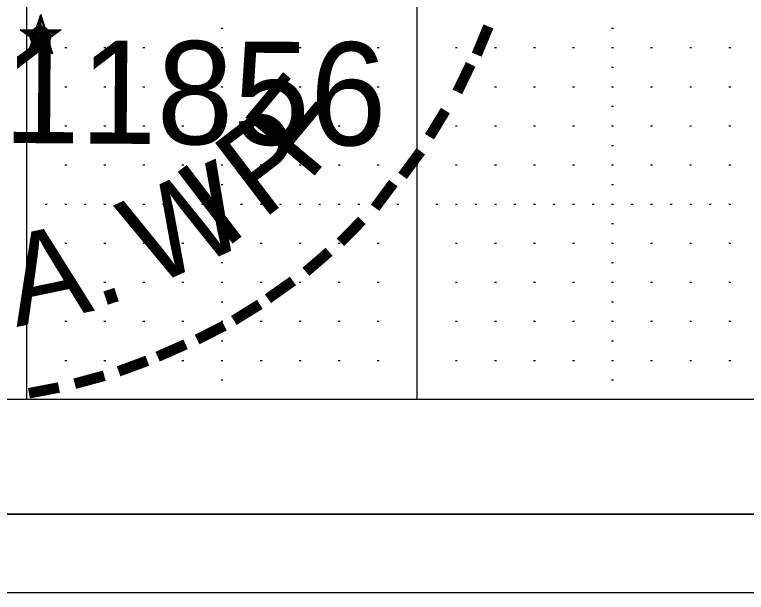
# Model space of a CAD drawing. Extents: x -1.3 to 32.1, y -0.2 to 20.7.
# Drawn here: x 23.714 to 25.588, y -0.2 to 1.277 of the extents above; entities that cross this region are included whole.
import ezdxf

# ---------------------------------------------------------------- set-up
doc = ezdxf.new("R2010")
doc.units = 0
for name, color, linetype in [('Level 1', 7, 'Continuous'), ('Level 37', 7, 'Continuous'), ('Level 49', 7, 'Continuous'), ('Level 5', 7, 'Continuous'), ('Level 50', 7, 'Continuous'), ('Level 6', 7, 'Continuous'), ('Level 62', 7, 'Continuous'), ('Level 63', 7, 'Continuous')]:
    doc.layers.add(name, color=color, linetype=linetype)

msp = doc.modelspace()

# ---------------------------------------------------------------- linework, layer by layer
at = {"layer": 'Level 1'}
msp.add_line((31.617, -0.001), (-0.001, -0.001), dxfattribs=at)
at = {"layer": 'Level 37'}
msp.add_line((31.618, -0.001), (-0.001, -0.001), dxfattribs=at)
at = {"layer": 'Level 49'}
for p, q in [((23.7815, 1.2774), (23.7722, 1.2386)), ((23.7815, 1.2774), (23.7741, 1.2386)), ((23.7815, 1.2774), (23.7778, 1.2386)), ((23.7815, 1.2201), (23.7815, 1.2774)), ((23.7815, 1.2774), (23.7889, 1.2386)), ((23.7815, 1.2774), (23.7889, 1.2386)), ((23.7815, 1.2774), (23.7815, 1.2386)), ((23.7278, 1.2386), (23.7815, 1.2201)), ((23.7278, 1.2386), (23.7667, 1.2349)), ((23.7278, 1.2386), (23.7667, 1.2312)), ((23.7278, 1.2386), (23.7648, 1.2275)), ((23.7278, 1.2386), (23.7648, 1.2238)), ((23.7278, 1.2386), (23.763, 1.2201)), ((23.7278, 1.2386), (23.763, 1.2164)), ((23.8333, 1.2386), (23.7815, 1.2201)), ((23.8333, 1.2386), (23.787, 1.2349)), ((23.8333, 1.2386), (23.7889, 1.2312)), ((23.8333, 1.2386), (23.7889, 1.2275)), ((23.8333, 1.2386), (23.8, 1.2256)), ((23.8333, 1.2386), (23.8018, 1.2201)), ((23.8333, 1.2386), (23.8037, 1.2201)), ((23.7482, 1.1775), (23.7815, 1.2201)), ((23.7482, 1.1775), (23.7648, 1.2201)), ((23.8111, 1.1775), (23.7815, 1.2201)), ((23.8111, 1.1775), (23.7926, 1.2201)), ((23.8111, 1.1775), (23.7944, 1.2201)), ((23.7482, 1.1775), (23.7667, 1.2127)), ((23.7482, 1.1775), (23.7704, 1.2127)), ((23.7482, 1.1775), (23.7741, 1.209)), ((23.7482, 1.1775), (23.7796, 1.209)), ((23.7482, 1.1775), (23.7815, 1.2053)), ((23.8111, 1.1775), (23.7796, 1.209)), ((23.8111, 1.1775), (23.7796, 1.2053)), ((23.8111, 1.1775), (23.7852, 1.209)), ((23.8111, 1.1775), (23.7889, 1.2127))]:
    msp.add_line(p, q, dxfattribs=at)
msp.add_lwpolyline([(23.7815, 1.2774), (23.8111, 1.1775), (23.7278, 1.2386), (23.8333, 1.2386), (23.7482, 1.1775), (23.7815, 1.2774)], dxfattribs=at)
for radius in [0.0258, 0.0234, 0.0217, 0.0199, 0.0173, 0.0161, 0.0149, 0.0128, 0.0112, 0.00931, 0.00743, 0.00554, 0.00444, 0.00216]:
    msp.add_circle((23.7802, 1.2214), radius, dxfattribs=at)
at = {"layer": 'Level 5'}
for p, q in [((24.2425, 1.243), (24.2475, 1.243)), ((25.2425, 1.243), (25.2475, 1.243)), ((23.8425, 1.193), (23.8475, 1.193)), ((23.9425, 1.193), (23.9475, 1.193)), ((24.0425, 1.193), (24.0475, 1.193)), ((24.1425, 1.193), (24.1475, 1.193)), ((24.2425, 1.193), (24.2475, 1.193)), ((24.3425, 1.193), (24.3475, 1.193)), ((24.4425, 1.193), (24.4475, 1.193)), ((24.5425, 1.193), (24.5475, 1.193)), ((24.6425, 1.193), (24.6475, 1.193)), ((24.8425, 1.193), (24.8475, 1.193)), ((24.9425, 1.193), (24.9475, 1.193)), ((25.0425, 1.193), (25.0475, 1.193)), ((25.1425, 1.193), (25.1475, 1.193)), ((25.2425, 1.193), (25.2475, 1.193)), ((25.3425, 1.193), (25.3475, 1.193)), ((25.4425, 1.193), (25.4475, 1.193)), ((25.5425, 1.193), (25.5475, 1.193)), ((24.2425, 1.143), (24.2475, 1.143)), ((25.2425, 1.143), (25.2475, 1.143)), ((23.8425, 1.093), (23.8475, 1.093)), ((23.9425, 1.093), (23.9475, 1.093)), ((24.0425, 1.093), (24.0475, 1.093)), ((24.1425, 1.093), (24.1475, 1.093)), ((24.2425, 1.093), (24.2475, 1.093)), ((24.3425, 1.093), (24.3475, 1.093)), ((24.4425, 1.093), (24.4475, 1.093)), ((24.5425, 1.093), (24.5475, 1.093)), ((24.6425, 1.093), (24.6475, 1.093)), ((24.8425, 1.093), (24.8475, 1.093)), ((24.9425, 1.093), (24.9475, 1.093)), ((25.0425, 1.093), (25.0475, 1.093)), ((25.1425, 1.093), (25.1475, 1.093)), ((25.2425, 1.093), (25.2475, 1.093)), ((25.3425, 1.093), (25.3475, 1.093)), ((25.4425, 1.093), (25.4475, 1.093)), ((25.5425, 1.093), (25.5475, 1.093)), ((24.2425, 1.043), (24.2475, 1.043)), ((25.2425, 1.043), (25.2475, 1.043)), ((23.8425, 0.993), (23.8475, 0.993)), ((23.9425, 0.993), (23.9475, 0.993)), ((24.0425, 0.993), (24.0475, 0.993)), ((24.1425, 0.993), (24.1475, 0.993)), ((24.2425, 0.993), (24.2475, 0.993)), ((24.3425, 0.993), (24.3475, 0.993)), ((24.4425, 0.993), (24.4475, 0.993)), ((24.5425, 0.993), (24.5475, 0.993)), ((24.6425, 0.993), (24.6475, 0.993)), ((24.8425, 0.993), (24.8475, 0.993)), ((24.9425, 0.993), (24.9475, 0.993)), ((25.0425, 0.993), (25.0475, 0.993)), ((25.1425, 0.993), (25.1475, 0.993)), ((25.2425, 0.993), (25.2475, 0.993)), ((25.3425, 0.993), (25.3475, 0.993)), ((25.4425, 0.993), (25.4475, 0.993)), ((25.5425, 0.993), (25.5475, 0.993)), ((24.2425, 0.943), (24.2475, 0.943)), ((25.2425, 0.943), (25.2475, 0.943)), ((23.8425, 0.893), (23.8475, 0.893)), ((23.9425, 0.893), (23.9475, 0.893)), ((24.0425, 0.893), (24.0475, 0.893)), ((24.1425, 0.893), (24.1475, 0.893)), ((24.2425, 0.893), (24.2475, 0.893)), ((24.3425, 0.893), (24.3475, 0.893)), ((24.4425, 0.893), (24.4475, 0.893)), ((24.5425, 0.893), (24.5475, 0.893)), ((24.6425, 0.893), (24.6475, 0.893)), ((24.8425, 0.893), (24.8475, 0.893)), ((24.9425, 0.893), (24.9475, 0.893)), ((25.0425, 0.893), (25.0475, 0.893)), ((25.1425, 0.893), (25.1475, 0.893)), ((25.2425, 0.893), (25.2475, 0.893)), ((25.3425, 0.893), (25.3475, 0.893)), ((25.4425, 0.893), (25.4475, 0.893)), ((25.5425, 0.893), (25.5475, 0.893)), ((24.2425, 0.843), (24.2475, 0.843)), ((25.2425, 0.843), (25.2475, 0.843)), ((23.7925, 0.793), (23.7975, 0.793)), ((23.8425, 0.793), (23.8475, 0.793)), ((23.8925, 0.793), (23.8975, 0.793)), ((23.9425, 0.793), (23.9475, 0.793)), ((23.9925, 0.793), (23.9975, 0.793)), ((24.0425, 0.793), (24.0475, 0.793)), ((24.0925, 0.793), (24.0975, 0.793)), ((24.1425, 0.793), (24.1475, 0.793)), ((24.1925, 0.793), (24.1975, 0.793)), ((24.2425, 0.793), (24.2475, 0.793)), ((24.2925, 0.793), (24.2975, 0.793)), ((24.3425, 0.793), (24.3475, 0.793)), ((24.3925, 0.793), (24.3975, 0.793)), ((24.4425, 0.793), (24.4475, 0.793)), ((24.4925, 0.793), (24.4975, 0.793)), ((24.5425, 0.793), (24.5475, 0.793)), ((24.5925, 0.793), (24.5975, 0.793)), ((24.6425, 0.793), (24.6475, 0.793)), ((24.6925, 0.793), (24.6975, 0.793)), ((24.7925, 0.793), (24.7975, 0.793)), ((24.8425, 0.793), (24.8475, 0.793)), ((24.8925, 0.793), (24.8975, 0.793)), ((24.9425, 0.793), (24.9475, 0.793)), ((24.9925, 0.793), (24.9975, 0.793)), ((25.0425, 0.793), (25.0475, 0.793)), ((25.0925, 0.793), (25.0975, 0.793)), ((25.1425, 0.793), (25.1475, 0.793)), ((25.1925, 0.793), (25.1975, 0.793)), ((25.2425, 0.793), (25.2475, 0.793)), ((25.2925, 0.793), (25.2975, 0.793)), ((25.3425, 0.793), (25.3475, 0.793)), ((25.3925, 0.793), (25.3975, 0.793)), ((25.4425, 0.793), (25.4475, 0.793)), ((25.4925, 0.793), (25.4975, 0.793)), ((25.5425, 0.793), (25.5475, 0.793)), ((24.2425, 0.743), (24.2475, 0.743)), ((25.2425, 0.743), (25.2475, 0.743)), ((23.8425, 0.693), (23.8475, 0.693)), ((23.9425, 0.693), (23.9475, 0.693)), ((24.0425, 0.693), (24.0475, 0.693)), ((24.1425, 0.693), (24.1475, 0.693)), ((24.2425, 0.693), (24.2475, 0.693)), ((24.3425, 0.693), (24.3475, 0.693)), ((24.4425, 0.693), (24.4475, 0.693)), ((24.5425, 0.693), (24.5475, 0.693)), ((24.6425, 0.693), (24.6475, 0.693)), ((24.8425, 0.693), (24.8475, 0.693)), ((24.9425, 0.693), (24.9475, 0.693)), ((25.0425, 0.693), (25.0475, 0.693)), ((25.1425, 0.693), (25.1475, 0.693)), ((25.2425, 0.693), (25.2475, 0.693)), ((25.3425, 0.693), (25.3475, 0.693)), ((25.4425, 0.693), (25.4475, 0.693)), ((25.5425, 0.693), (25.5475, 0.693)), ((24.2425, 0.643), (24.2475, 0.643)), ((25.2425, 0.643), (25.2475, 0.643)), ((23.8425, 0.593), (23.8475, 0.593)), ((23.9425, 0.593), (23.9475, 0.593)), ((24.0425, 0.593), (24.0475, 0.593)), ((24.1425, 0.593), (24.1475, 0.593)), ((24.2425, 0.593), (24.2475, 0.593)), ((24.3425, 0.593), (24.3475, 0.593)), ((24.4425, 0.593), (24.4475, 0.593)), ((24.5425, 0.593), (24.5475, 0.593)), ((24.6425, 0.593), (24.6475, 0.593)), ((24.8425, 0.593), (24.8475, 0.593)), ((24.9425, 0.593), (24.9475, 0.593)), ((25.0425, 0.593), (25.0475, 0.593)), ((25.1425, 0.593), (25.1475, 0.593)), ((25.2425, 0.593), (25.2475, 0.593)), ((25.3425, 0.593), (25.3475, 0.593)), ((25.4425, 0.593), (25.4475, 0.593)), ((25.5425, 0.593), (25.5475, 0.593)), ((24.2425, 0.543), (24.2475, 0.543)), ((25.2425, 0.543), (25.2475, 0.543)), ((23.8425, 0.493), (23.8475, 0.493)), ((23.9425, 0.493), (23.9475, 0.493)), ((24.0425, 0.493), (24.0475, 0.493)), ((24.1425, 0.493), (24.1475, 0.493)), ((24.2425, 0.493), (24.2475, 0.493)), ((24.3425, 0.493), (24.3475, 0.493)), ((24.4425, 0.493), (24.4475, 0.493)), ((24.5425, 0.493), (24.5475, 0.493)), ((24.6425, 0.493), (24.6475, 0.493)), ((24.8425, 0.493), (24.8475, 0.493)), ((24.9425, 0.493), (24.9475, 0.493)), ((25.0425, 0.493), (25.0475, 0.493)), ((25.1425, 0.493), (25.1475, 0.493)), ((25.2425, 0.493), (25.2475, 0.493)), ((25.3425, 0.493), (25.3475, 0.493)), ((25.4425, 0.493), (25.4475, 0.493)), ((25.5425, 0.493), (25.5475, 0.493)), ((24.2425, 0.443), (24.2475, 0.443)), ((25.2425, 0.443), (25.2475, 0.443)), ((23.8425, 0.393), (23.8475, 0.393)), ((23.9425, 0.393), (23.9475, 0.393)), ((24.0425, 0.393), (24.0475, 0.393)), ((24.1425, 0.393), (24.1475, 0.393)), ((24.2425, 0.393), (24.2475, 0.393)), ((24.3425, 0.393), (24.3475, 0.393)), ((24.4425, 0.393), (24.4475, 0.393)), ((24.5425, 0.393), (24.5475, 0.393)), ((24.6425, 0.393), (24.6475, 0.393)), ((24.8425, 0.393), (24.8475, 0.393)), ((24.9425, 0.393), (24.9475, 0.393)), ((25.0425, 0.393), (25.0475, 0.393)), ((25.1425, 0.393), (25.1475, 0.393)), ((25.2425, 0.393), (25.2475, 0.393)), ((25.3425, 0.393), (25.3475, 0.393)), ((25.4425, 0.393), (25.4475, 0.393)), ((25.5425, 0.393), (25.5475, 0.393)), ((24.2425, 0.343), (24.2475, 0.343)), ((25.2425, 0.343), (25.2475, 0.343))]:
    msp.add_line(p, q, dxfattribs=at)
at = {"layer": 'Level 6'}
for p, q in [((23.745, 0.293), (23.745, 10.293)), ((24.745, 0.293), (24.745, 10.293)), ((31.617, 0.293), (-0.001, 0.293))]:
    msp.add_line(p, q, dxfattribs=at)
at = {"layer": 'Level 62'}
msp.add_line((-0.001, 0), (31.618, 0), dxfattribs=at)
at = {"layer": 'Level 63'}
msp.add_lwpolyline([(-1.263, -0.2005), (32.067, -0.2005), (32.067, 20.7465), (-1.263, 20.7465)], close=True, dxfattribs=at)

# ---------------------------------------------------------------- texts
at = {"layer": 'Level 49'}
for s, height, rotation, p in [('-', 0.2398, 247.4911, (24.8471, 1.2959)), ('No. 11856', 0.26378, 359.6024, (23.0378, 0.9537)), ('-', 0.2398, 244.2221, (24.8045, 1.2034)), ('-', 0.2398, 238.6736, (24.7453, 1.0924)), ('-', 0.2398, 233.4476, (24.688, 0.9944)), ('-', 0.2398, 233.4476, (24.6177, 0.913)), ('-', 0.2398, 225.3677, (24.5474, 0.826)), ('-', 0.2398, 220.6875, (24.4697, 0.7502)), ('-', 0.2398, 215.3387, (24.3846, 0.6799)), ('-', 0.2398, 211.8515, (24.305, 0.6225)), ('-', 0.2398, 206.9592, (24.2218, 0.5707)), ('-', 0.2398, 203.854, (24.1274, 0.5245)), ('-', 0.2398, 200.3208, (24.0349, 0.4838)), ('-', 0.2398, 195.0767, (23.9332, 0.4468)), ('-', 0.2398, 190.8882, (23.824, 0.4172))]:
    msp.add_text(s, height=height, rotation=rotation, dxfattribs=at).set_placement(p)
at = {"layer": 'Level 50'}
for s, rotation, p in [('F', 50.1538, (24.466, 0.8464)), ('P', 37.377, (24.3476, 0.7502)), ('W', 24.6002, (24.0608, 0.5781)), ('I', 37.377, (24.2495, 0.6743)), ('A', 11.8234, (23.7186, 0.4782)), ('.', 18.2118, (23.9258, 0.5263))]:
    msp.add_text(s, height=0.2312, rotation=rotation, dxfattribs=at).set_placement(p)

doc.saveas('drawing.dxf')
